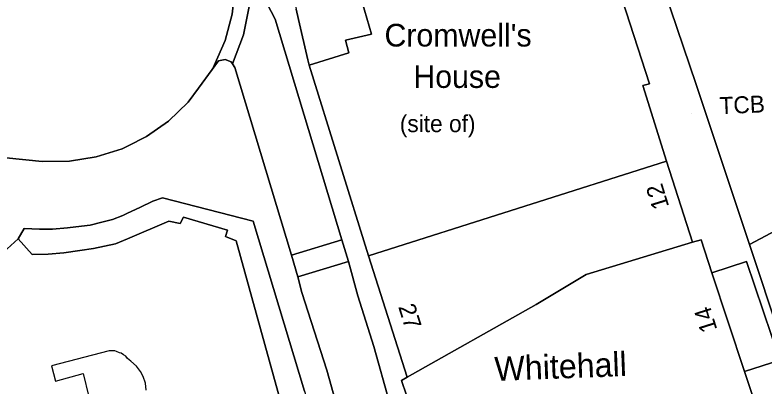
# Model space of a CAD drawing. Extents: x 529240 to 530363, y 179600 to 180767.
# Drawn here: x 529990.1 to 530056.2, y 180289 to 180321.7 of the extents above; entities that cross this region are included whole.
import ezdxf

# ---------------------------------------------------------------- set-up
doc = ezdxf.new("R2010")
doc.units = 0
for name, color, linetype in [('Building', 7, 'Continuous'), ('General surface', 7, 'Continuous'), ('Road Or Track', 7, 'Continuous'), ('Roadside', 7, 'Continuous'), ('Structure', 7, 'Continuous'), ('Unclassified', 7, 'Continuous')]:
    doc.layers.add(name, color=color, linetype=linetype)

msp = doc.modelspace()

# ---------------------------------------------------------------- linework, layer by layer
at = {"layer": 'Building'}
for points in [[(530047.6, 180308.85), (530045.5, 180315.5), (530046.1, 180315.65), (530042.65, 180326.3), (530042.2, 180326.2), (530040, 180332.9), (530039.3, 180332.65)], [(530020.1, 180325), (530021.55, 180320.05), (530019.25, 180319.5), (530019.55, 180318.4), (530016.05, 180317.3), (530021.3, 180300.5), (530047.6, 180308.85), (530045.5, 180315.5), (530046.1, 180315.65), (530042.65, 180326.3)], [(530020.1, 180325), (530021.55, 180320.05), (530019.25, 180319.5), (530019.55, 180318.4), (530016.05, 180317.3)], [(530016.05, 180317.3), (530021.3, 180300.5)], [(530021.3, 180300.5), (530047.6, 180308.85)], [(530049.9, 180301.7), (530047.6, 180308.85)], [(530015.05, 180282.15), (530009.6, 180301.8), (530008.65, 180302.2), (530008.85, 180302.75), (530004.95, 180303.9), (530004.65, 180303.35), (530003.65, 180303.55), (530000, 180302), (529998.95, 180301.55), (529997, 180301.15), (529995.8, 180300.95), (529994.4, 180300.75), (529993, 180300.65), (529991.6, 180300.6), (529990.35, 180302), (529989.05, 180300.8)], [(529990.35, 180302), (529991.6, 180300.6), (529993, 180300.65), (529994.4, 180300.75), (529995.8, 180300.95), (529997, 180301.15), (529998.95, 180301.55), (530000, 180302), (530003.65, 180303.55), (530004.65, 180303.35), (530004.95, 180303.9), (530008.85, 180302.75), (530008.65, 180302.2), (530009.6, 180301.8), (530015.05, 180282.15), (530015.55, 180281.9), (530013.8, 180278.75), (530013.35, 180279), (530002.65, 180276.05), (530002.9, 180275.55), (530002.6, 180275.5), (530002.65, 180275.2), (530001.9, 180275)], [(529989.05, 180300.8), (529990.35, 180302)], [(530024.7, 180289.8), (530036.1, 180296.2), (530040.5, 180298.85), (530049.9, 180301.7)], [(530049.9, 180301.7), (530050.65, 180301.9), (530051.6, 180299)], [(530021.3, 180300.5), (530024.7, 180289.8)], [(530051.6, 180299), (530054.65, 180300), (530057.6, 180291.3), (530054.5, 180290.3)], [(530051.6, 180299), (530054.5, 180290.3)], [(530001.65, 180288.65), (530001.6, 180289.25), (530001.4, 180289.85), (530001.15, 180290.3), (530000.8, 180290.75), (530000.3, 180291.2), (530000, 180291.45), (529999.85, 180291.65), (529999.65, 180291.75), (529999.45, 180291.9), (529999.3, 180291.95), (529999.05, 180292.05), (529998.9, 180292.1), (529998.4, 180292.1), (529993.3, 180290.8), (529993.65, 180289.45), (529996.1, 180290.1), (529997.1, 180286)], [(530001.65, 180288.65), (530001.6, 180289.25), (530001.4, 180289.85), (530001.15, 180290.3), (530000.8, 180290.75), (530000.3, 180291.2), (530000, 180291.45), (529999.85, 180291.65), (529999.65, 180291.75), (529999.45, 180291.9), (529999.3, 180291.95), (529999.05, 180292.05), (529998.9, 180292.1), (529998.4, 180292.1), (529993.3, 180290.8), (529993.65, 180289.45), (529996.1, 180290.1), (529997.1, 180286)], [(530024.65, 180288.2), (530024.2, 180289.5), (530024.7, 180289.8)], [(530054.5, 180290.3), (530055.6, 180286.95), (530055.3, 180286.8)]]:
    msp.add_lwpolyline(points, dxfattribs=at)
for points in [[(530047.6, 180308.85), (530021.3, 180300.5), (530024.7, 180289.8), (530036.1, 180296.2), (530040.5, 180298.85), (530049.9, 180301.7)], [(530054.5, 180290.3), (530051.6, 180299), (530050.65, 180301.9), (530049.9, 180301.7), (530040.5, 180298.85), (530036.1, 180296.2), (530024.7, 180289.8), (530024.2, 180289.5), (530024.65, 180288.2), (530028.35, 180277.15), (530028.7, 180276.2), (530029.25, 180274.6), (530042.05, 180279.4), (530041.5, 180281.5), (530045.95, 180283.2), (530055.3, 180286.8), (530055.6, 180286.95)], [(530054.5, 180290.3), (530057.6, 180291.3), (530054.65, 180300), (530051.6, 180299)]]:
    msp.add_lwpolyline(points, close=True, dxfattribs=at)
at = {"layer": 'General surface'}
msp.add_lwpolyline([(530014.9, 180322.25), (530015.11, 180321.34), (530015.94, 180317.77), (530016.05, 180317.3), (530019.55, 180318.4), (530019.25, 180319.5), (530021.55, 180320.05), (530020.1, 180325), (530013.9, 180326.8)], close=True, dxfattribs=at)
for points in [[(530015.65, 180288.55), (530011.1, 180303.55), (530003.1, 180305.6), (530002.25, 180305.3), (530001.1, 180304.75), (530000, 180304.25), (529999.6, 180304.05), (529998.7, 180303.7), (529997.75, 180303.45), (529996.7, 180303.2), (529995.45, 180303.05), (529994.7, 180302.95), (529993.4, 180302.85), (529992.25, 180302.85), (529990.9, 180302.9), (529990.35, 180302), (529991.6, 180300.6), (529993, 180300.65), (529994.4, 180300.75), (529995.8, 180300.95), (529997, 180301.15), (529998.95, 180301.55), (530000, 180302), (530003.65, 180303.55), (530004.65, 180303.35), (530004.95, 180303.9), (530008.85, 180302.75), (530008.65, 180302.2), (530009.6, 180301.8), (530015.05, 180282.15)], [(530001.65, 180288.65), (530001.6, 180289.25), (530001.4, 180289.85), (530001.15, 180290.3), (530000.8, 180290.75), (530000.3, 180291.2), (530000, 180291.45), (529999.85, 180291.65), (529999.65, 180291.75), (529999.45, 180291.9), (529999.3, 180291.95), (529999.05, 180292.05), (529998.9, 180292.1), (529998.4, 180292.1), (529993.3, 180290.8), (529993.65, 180289.45), (529996.1, 180290.1), (529997.1, 180286)]]:
    msp.add_lwpolyline(points, dxfattribs=at)
at = {"layer": 'Road Or Track'}
for points in [[(530054.93, 180301.48), (530050.23, 180315.6), (530042.9, 180337.2), (530041.94, 180339.4), (530040.61, 180341.4), (530040.11, 180341.93), (530038.97, 180343.14), (530037.06, 180344.58), (530037.05, 180344.58), (530034.92, 180345.67), (530032.63, 180346.38), (530030.25, 180346.69)], [(530042.9, 180337.2), (530050.23, 180315.6), (530054.93, 180301.48), (530067.51, 180308.15)], [(530007.49, 180316.92), (530007.65, 180317.28), (530008.62, 180319.47), (530009.24, 180321.79), (530009.51, 180324.17), (530009.43, 180326.44)], [(529976.87, 180324.9), (529972.82, 180321.51), (529986.4, 180306.51), (529986.81, 180306.06), (529989.29, 180309.12), (529992.48, 180308.8), (529994.88, 180308.83), (529997.24, 180309.21), (529999.53, 180309.94), (530000, 180310.17), (530001.68, 180311.01), (530003.64, 180312.38), (530005.38, 180314.03), (530006.29, 180315.27), (530007.49, 180316.92), (530007.65, 180317.28), (530008.62, 180319.47), (530009.24, 180321.79)], [(530009.29, 180317.42), (530010.25, 180319.98), (530010.79, 180322.62), (530010.91, 180324.1)], [(530010.91, 180324.1), (530012.34, 180322.7), (530013.04, 180321.37), (530018.93, 180301.9)], [(530009.29, 180317.42), (530009.17, 180317.59), (530008.62, 180317.81), (530008.04, 180317.68), (530007.49, 180316.92)], [(530007.49, 180316.92), (530006.29, 180315.27), (530005.38, 180314.03), (530003.64, 180312.38), (530001.68, 180311.01), (530000, 180310.17), (529999.53, 180309.94), (529997.24, 180309.21), (529994.88, 180308.83), (529992.48, 180308.8), (529989.29, 180309.12), (529986.81, 180306.06)], [(530014.48, 180300.56), (530009.5, 180317.1), (530009.29, 180317.42)], [(530014.48, 180300.56), (530018.93, 180301.9)], [(530018.93, 180301.9), (530019.51, 180299.99)], [(530057.63, 180293.36), (530054.93, 180301.48)], [(530015.06, 180298.64), (530014.48, 180300.56)], [(530015.06, 180298.64), (530019.51, 180299.99)], [(530019.51, 180299.99), (530020.35, 180296.95), (530021.75, 180292.5), (530023.15, 180287.55), (530024.6, 180282.6), (530025.7, 180279.2)], [(530018.6, 180277.1), (530019.05, 180278.05), (530019.15, 180278.3), (530019.45, 180279.3), (530019.65, 180280.25), (530019.65, 180281.3), (530019.55, 180282.3), (530019.5, 180283.4), (530019.35, 180284.2), (530017.6, 180290.4), (530015.4, 180297.25), (530015.06, 180298.64)]]:
    msp.add_lwpolyline(points, dxfattribs=at)
for points in [[(530007.49, 180316.92), (530008.04, 180317.68), (530008.62, 180317.81), (530009.17, 180317.59), (530009.29, 180317.42), (530010.25, 180319.98), (530010.79, 180322.62), (530010.91, 180324.1), (530010.75, 180324.25), (530009.79, 180325.3), (530009.43, 180326.44), (530009.51, 180324.17), (530009.24, 180321.79), (530008.62, 180319.47), (530007.65, 180317.28)], [(530014.48, 180300.56), (530018.93, 180301.9), (530013.04, 180321.37), (530012.34, 180322.7), (530010.91, 180324.1), (530010.79, 180322.62), (530010.25, 180319.98), (530009.29, 180317.42), (530009.5, 180317.1)], [(530070.58, 180297.76), (530070.34, 180298.61), (530070.31, 180299.02), (530070.55, 180299.56), (530069.6, 180302.18), (530069.12, 180302.92), (530068.72, 180304.29), (530067.95, 180306.6), (530067.51, 180308.15), (530054.93, 180301.48), (530057.63, 180293.36)], [(530015.06, 180298.64), (530019.51, 180299.99), (530018.93, 180301.9), (530014.48, 180300.56)], [(530018.6, 180277.1), (530025.7, 180279.2), (530024.6, 180282.6), (530023.15, 180287.55), (530021.75, 180292.5), (530020.35, 180296.95), (530019.51, 180299.99), (530015.06, 180298.64), (530015.4, 180297.25), (530017.6, 180290.4), (530019.35, 180284.2), (530019.5, 180283.4), (530019.55, 180282.3), (530019.65, 180281.3), (530019.65, 180280.25), (530019.45, 180279.3), (530019.15, 180278.3), (530019.05, 180278.05)]]:
    msp.add_lwpolyline(points, close=True, dxfattribs=at)
at = {"layer": 'Roadside'}
for points in [[(530057.63, 180293.36), (530054.93, 180301.48), (530050.23, 180315.6), (530042.9, 180337.2)], [(530042.65, 180326.3), (530046.1, 180315.65), (530045.5, 180315.5), (530047.6, 180308.85), (530049.9, 180301.7), (530050.65, 180301.9), (530051.6, 180299), (530054.65, 180300), (530057.6, 180291.3), (530054.5, 180290.3), (530055.6, 180286.95), (530055.3, 180286.8), (530059.8, 180273.05)], [(530012.34, 180322.7), (530013.04, 180321.37), (530018.93, 180301.9), (530019.51, 180299.99), (530020.35, 180296.95), (530021.75, 180292.5), (530023.15, 180287.55)], [(530024.65, 180288.2), (530024.2, 180289.5), (530024.7, 180289.8), (530021.3, 180300.5), (530016.05, 180317.3), (530015.94, 180317.77), (530015.11, 180321.34), (530014.9, 180322.25)], [(530019.35, 180284.2), (530017.6, 180290.4), (530015.4, 180297.25), (530015.06, 180298.64), (530014.48, 180300.56), (530009.5, 180317.1), (530009.29, 180317.42), (530009.17, 180317.59), (530008.62, 180317.81), (530008.04, 180317.68), (530007.49, 180316.92), (530006.29, 180315.27), (530005.38, 180314.03), (530003.64, 180312.38), (530001.68, 180311.01), (530000, 180310.17), (529999.53, 180309.94), (529997.24, 180309.21), (529994.88, 180308.83), (529992.48, 180308.8), (529989.29, 180309.12)], [(529989.05, 180300.8), (529990.35, 180302), (529990.9, 180302.9), (529992.25, 180302.85), (529993.4, 180302.85), (529994.7, 180302.95), (529995.45, 180303.05), (529996.7, 180303.2), (529997.75, 180303.45), (529998.7, 180303.7), (529999.6, 180304.05), (530000, 180304.25), (530001.1, 180304.75), (530002.25, 180305.3), (530003.1, 180305.6), (530011.1, 180303.55), (530015.65, 180288.55)]]:
    msp.add_lwpolyline(points, dxfattribs=at)
at = {"layer": 'Structure'}
msp.add_line((530049.77, 180313.01), (530049.77, 180313.01), dxfattribs=at)
at = {"layer": 'Unclassified'}
for points in [[(530016.05, 180317.3), (530015.94, 180317.77), (530015.11, 180321.34), (530014.9, 180322.25)], [(530054.93, 180301.48), (530067.51, 180308.15)], [(529990.35, 180302), (529990.9, 180302.9), (529992.25, 180302.85), (529993.4, 180302.85), (529994.7, 180302.95), (529995.45, 180303.05), (529996.7, 180303.2), (529997.75, 180303.45), (529998.7, 180303.7), (529999.6, 180304.05), (530000, 180304.25), (530001.1, 180304.75), (530002.25, 180305.3), (530003.1, 180305.6), (530011.1, 180303.55)], [(530011.1, 180303.55), (530015.65, 180288.55), (530017.65, 180281.9), (530015.79, 180278.7), (530014.65, 180276.75), (530002.3, 180273.45)]]:
    msp.add_lwpolyline(points, dxfattribs=at)

# ---------------------------------------------------------------- texts
at = {"layer": 'Structure'}
msp.add_text('TCB', height=1.5, rotation=2.4, dxfattribs=at).set_placement((530052.31, 180312.98))
at = {"layer": 'Unclassified'}
for s, height, p in [("Cromwell's", 2, (530022.7, 180318.95)), ('House', 2, (530025.25, 180315.3)), ('(site of)', 1.5, (530024.05, 180311.4))]:
    msp.add_text(s, height=height, dxfattribs=at).set_placement(p)
for s, height, rotation, p in [('12', 1.5, 107.2, (530047.85, 180304.85)), ('27', 1.5, 287.6, (530023.9, 180296)), ('14', 1.5, 107.5, (530052.1, 180294)), ('Whitehall', 2.125, 2.2, (530032.45, 180289.45))]:
    msp.add_text(s, height=height, rotation=rotation, dxfattribs=at).set_placement(p)

doc.saveas('drawing.dxf')
